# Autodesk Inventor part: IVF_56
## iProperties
Created: 2010-01
Part Number: IVF_56
Material: Sondermaterial siehe Beschreibung
Document SubType Name: Blech
Designer: Gawin
Surface Area: 111.786 cm^2
Volume: 3.82814 cm^3
Sheet Metal Rule: R2,5
Flat Pattern Width: 5.44673 cm
Flat Pattern Length: 10.8906 cm
Flat Pattern Area: 59.3183 cm^2
Author: Gawin
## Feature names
1. Grobblech2
2. Grobblech3
3. Biegung1
4. Grobblech4
5. Biegung2
6. Grobblech5
7. Biegung3
8. Ausklinkung1
